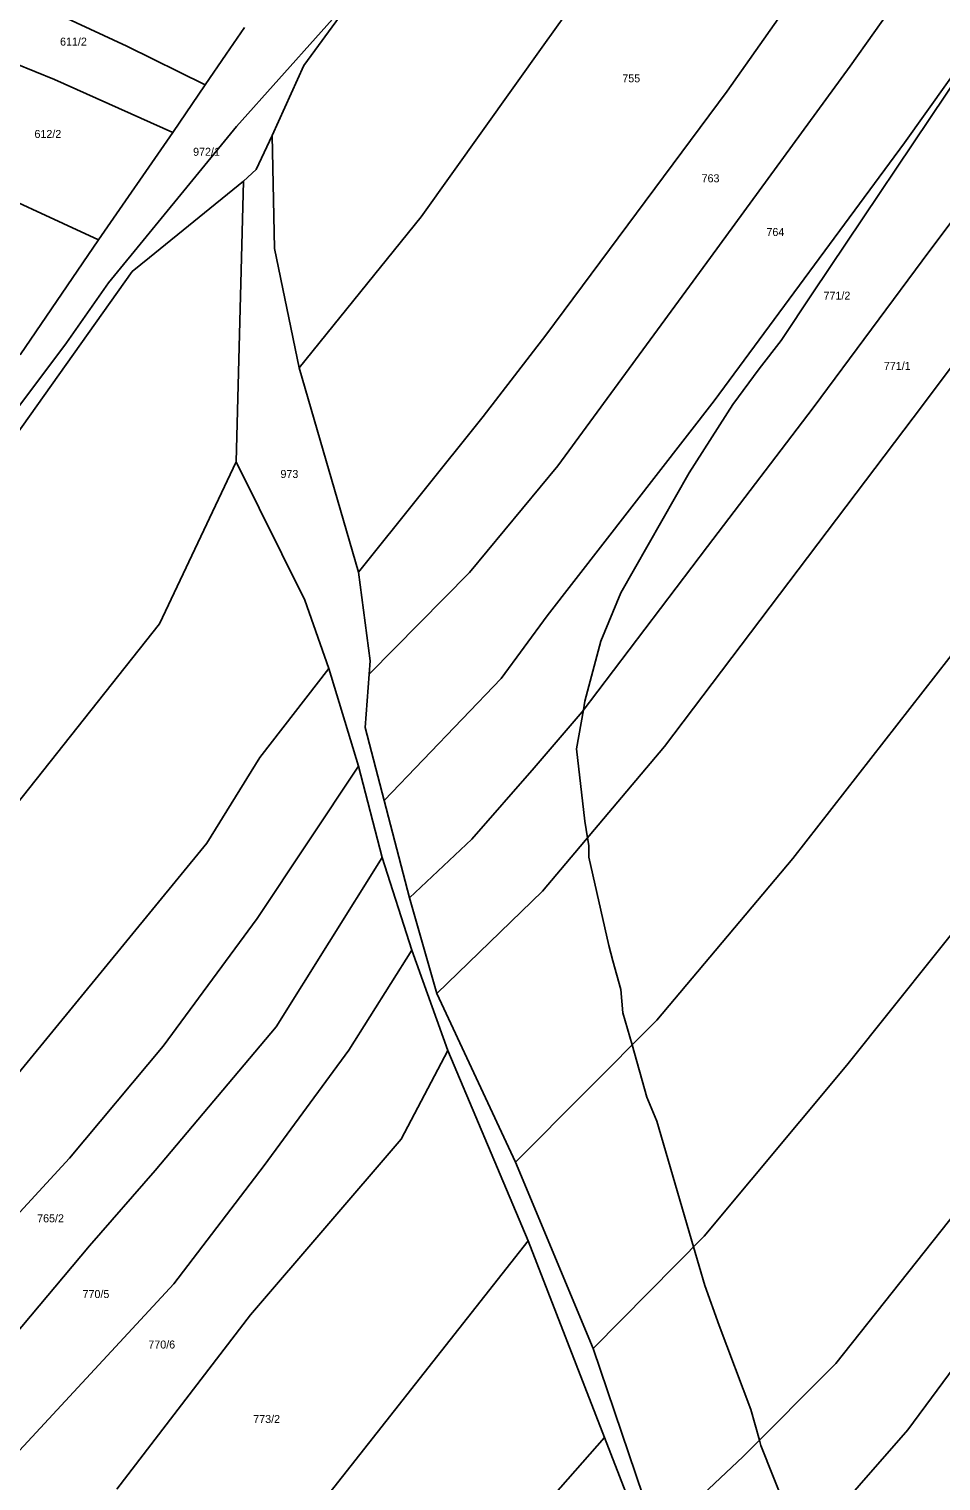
# Model space of a CAD drawing. Extents: x -749173 to -746119, y -1132678 to -1130338.
# Drawn here: x -748172.9 to -747979.1, y -1131515.5 to -1131207.1 of the extents above; entities that cross this region are included whole.
import ezdxf

# ---------------------------------------------------------------- set-up
doc = ezdxf.new("R2010")
doc.units = 0
for name, color, linetype in [('Vrstva 1', 7, 'Continuous'), ('Vrstva 18', 7, 'Continuous'), ('Vrstva 52', 7, 'Continuous'), ('Vrstva 6', 7, 'Continuous')]:
    doc.layers.add(name, color=color, linetype=linetype)

msp = doc.modelspace()

# ---------------------------------------------------------------- linework, layer by layer
at = {"layer": 'Vrstva 1'}
for points in [[(-748089.38, -1131180.54), (-748114.45, -1131214.85)], [(-748130.99, -1131212.41), (-748127.06, -1131206.76)], [(-748135.43, -1131218.94), (-748130.99, -1131212.41)], [(-748114.45, -1131214.85), (-748121.21, -1131229.7)], [(-748142.32, -1131229.06), (-748135.43, -1131218.94)], [(-748158.14, -1131251.87), (-748142.32, -1131229.06)], [(-748124.63, -1131236.91), (-748121.21, -1131229.7)], [(-748121.21, -1131229.7), (-748120.74, -1131253.68)], [(-748147.3, -1131255.64), (-748127.32, -1131239.4)], [(-748128.85, -1131299.01), (-748127.32, -1131239.4)], [(-748127.32, -1131239.4), (-748124.63, -1131236.91)], [(-748174.73, -1131276.29), (-748158.14, -1131251.87)], [(-748120.74, -1131253.68), (-748115.5, -1131279.07)], [(-748150.94, -1131258.6), (-748147.3, -1131255.64)], [(-748186.88, -1131309.09), (-748150.94, -1131258.6)], [(-748115.5, -1131279.07), (-748102.85, -1131322.48)], [(-748114.24, -1131328.44), (-748128.85, -1131299.01)], [(-748102.85, -1131322.48), (-748100.38, -1131341.3)], [(-748109.16, -1131342.95), (-748114.24, -1131328.44)], [(-748100.38, -1131341.3), (-748100.59, -1131344.15)], [(-748102.88, -1131363.67), (-748109.16, -1131342.95)], [(-748100.59, -1131344.15), (-748101.42, -1131355.5)], [(-748101.42, -1131355.5), (-748097.41, -1131370.99)], [(-748097.84, -1131383.08), (-748102.88, -1131363.67)], [(-748097.41, -1131370.99), (-748092.04, -1131391.66)], [(-748091.49, -1131402.75), (-748097.84, -1131383.08)], [(-748092.04, -1131391.66), (-748086.2, -1131411.99)], [(-748083.86, -1131424.07), (-748091.49, -1131402.75)], [(-748086.2, -1131411.99), (-748069.53, -1131447.82)], [(-748066.79, -1131464.53), (-748083.86, -1131424.07)], [(-748069.53, -1131447.82), (-748052.97, -1131487.38)], [(-748050.59, -1131506.3), (-748066.79, -1131464.53)], [(-748052.97, -1131487.38), (-748039.41, -1131527.57)], [(-748035.65, -1131544.85), (-748050.59, -1131506.3)]]:
    msp.add_lwpolyline(points, dxfattribs=at)
at = {"layer": 'Vrstva 52'}
for points in [[(-748101.82, -1131197.57), (-748128.75, -1131227.75), (-748156, -1131261), (-748164.94, -1131273.75), (-748191.69, -1131309.37), (-748224, -1131352.75), (-748231.25, -1131363), (-748232.94, -1131366.37), (-748237.19, -1131373.25), (-748246.12, -1131391.12), (-748246.24, -1131391.44), (-748246.42, -1131391.89), (-748259.31, -1131426.75), (-748266.56, -1131460), (-748269.56, -1131480), (-748271.25, -1131493.12), (-748271.53, -1131496.77), (-748272.98, -1131515.29), (-748274.31, -1131532.4)], [(-748009.25, -1131528.5), (-748017.37, -1131508), (-748017.68, -1131506.9), (-748019.5, -1131500.37), (-748026.25, -1131482.5), (-748029.25, -1131474), (-748031.65, -1131465.79), (-748039.44, -1131439.12), (-748041.56, -1131434), (-748044.74, -1131422.91), (-748046.69, -1131416.12), (-748047.12, -1131411.12), (-748048.79, -1131405.02), (-748049.69, -1131401.75), (-748053.94, -1131383), (-748053.94, -1131380.5), (-748054.19, -1131378.9), (-748054.75, -1131375.37), (-748056.5, -1131360), (-748055.07, -1131351.74), (-748054.75, -1131349.87), (-748051.37, -1131337.12), (-748047.12, -1131326.87), (-748032.62, -1131301.37), (-748023.31, -1131286.87), (-748017.75, -1131279.25), (-748013.06, -1131273.25), (-748006.31, -1131263.12), (-747974.37, -1131215.5)]]:
    msp.add_lwpolyline(points, dxfattribs=at)
at = {"layer": 'Vrstva 6'}
for points in [[(-748037.76, -1131174.55), (-748063.48, -1131210.43)], [(-748024.52, -1131220.29), (-747997.58, -1131182.04)], [(-747978.25, -1131186.55), (-747998.39, -1131214.99)], [(-747986.85, -1131231.25), (-747954.3, -1131185.56)], [(-748170.55, -1131202.15), (-748152.1, -1131210.73)], [(-748184.22, -1131210.98), (-748167.42, -1131217.79)], [(-748152.1, -1131210.73), (-748135.43, -1131218.94)], [(-748063.48, -1131210.43), (-748089.53, -1131247)], [(-748167.42, -1131217.79), (-748142.32, -1131229.06)], [(-747998.39, -1131214.99), (-748028.05, -1131255.6)], [(-748063.02, -1131272.11), (-748024.52, -1131220.29)], [(-747984.99, -1131289.67), (-747934.84, -1131222.88)], [(-747963.16, -1131229.8), (-747981.45, -1131254.14)], [(-748027.31, -1131286.05), (-747986.85, -1131231.25)], [(-748187.31, -1131238.43), (-748158.14, -1131251.87)], [(-748089.53, -1131247), (-748115.5, -1131279.07)], [(-747981.45, -1131254.14), (-748006.25, -1131287.53)], [(-748028.05, -1131255.6), (-748060.51, -1131299.88)], [(-748076.38, -1131289.39), (-748063.02, -1131272.11)], [(-748062.77, -1131331.73), (-748027.31, -1131286.05)], [(-748006.25, -1131287.53), (-748028.67, -1131317.02)], [(-748102.85, -1131322.48), (-748076.38, -1131289.39)], [(-748037.84, -1131359.52), (-747984.99, -1131289.67)], [(-748128.85, -1131299.01), (-748145.12, -1131333.41)], [(-748060.51, -1131299.88), (-748079.24, -1131322.55)], [(-748028.67, -1131317.02), (-748055.36, -1131352.12)], [(-748079.24, -1131322.55), (-748100.59, -1131344.15)], [(-748072.55, -1131345.05), (-748062.77, -1131331.73)], [(-747969.15, -1131330.2), (-748010.54, -1131383.33)], [(-748145.12, -1131333.41), (-748232.47, -1131443.55)], [(-748123.81, -1131361.87), (-748109.16, -1131342.95)], [(-748097.41, -1131370.99), (-748072.55, -1131345.05)], [(-748055.36, -1131352.12), (-748065.51, -1131364.02)], [(-748063.76, -1131390.25), (-748037.84, -1131359.52)], [(-748135.1, -1131380.02), (-748123.81, -1131361.87)], [(-748102.88, -1131363.67), (-748124.36, -1131396.05)], [(-748065.51, -1131364.02), (-748078.75, -1131379.21)], [(-748179.46, -1131434.11), (-748135.1, -1131380.02)], [(-748078.75, -1131379.21), (-748092.04, -1131391.66)], [(-748097.84, -1131383.08), (-748120.34, -1131419.08)], [(-748010.54, -1131383.33), (-748039.5, -1131417.64)], [(-748086.2, -1131411.99), (-748063.76, -1131390.25)], [(-747999.11, -1131427.19), (-747970.67, -1131391.64)], [(-748124.36, -1131396.05), (-748144.37, -1131423.16)], [(-748091.49, -1131402.75), (-748104.89, -1131424.02)], [(-748039.5, -1131417.64), (-748069.53, -1131447.82)], [(-748120.34, -1131419.08), (-748146.07, -1131449.57)], [(-748144.37, -1131423.16), (-748164.25, -1131446.94)], [(-748104.89, -1131424.02), (-748122.88, -1131448.54)], [(-748093.8, -1131442.91), (-748083.86, -1131424.07)], [(-748029.39, -1131463.51), (-747999.11, -1131427.19)], [(-747960.37, -1131438.84), (-748001.42, -1131490.57)], [(-748125.78, -1131480.26), (-748093.8, -1131442.91)], [(-748164.25, -1131446.94), (-748179.78, -1131463.77)], [(-748122.88, -1131448.54), (-748142.13, -1131473.68)], [(-748146.07, -1131449.57), (-748160.01, -1131465.57)], [(-748066.79, -1131464.53), (-748119.12, -1131530.98)], [(-748052.97, -1131487.38), (-748029.39, -1131463.51)], [(-747986.12, -1131504.66), (-747956.18, -1131464.19)], [(-748190.71, -1131502.08), (-748160.01, -1131465.57)], [(-748142.13, -1131473.68), (-748180.26, -1131514.82)], [(-748154.21, -1131517.27), (-748125.78, -1131480.26)], [(-748001.42, -1131490.57), (-748021.11, -1131510.35)], [(-748006.8, -1131528.34), (-747986.12, -1131504.66)], [(-748088.51, -1131549.4), (-748050.59, -1131506.3)], [(-748021.11, -1131510.35), (-748039.41, -1131527.57)]]:
    msp.add_lwpolyline(points, dxfattribs=at)

# ---------------------------------------------------------------- texts
at = {"layer": 'Vrstva 18'}
for s, p in [('611/2', (-748166.27, -1131210.59)), ('755', (-748046.8, -1131218.39)), ('612/2', (-748171.71, -1131230.21)), ('972/1', (-748138, -1131234)), ('763', (-748029.95, -1131239.63)), ('764', (-748016.17, -1131251.04)), ('771/2', (-748004.04, -1131264.57)), ('771/1', (-747991.22, -1131279.48)), ('973', (-748119.44, -1131302.45)), ('765/2', (-748171.14, -1131460.59)), ('770/5', (-748161.49, -1131476.68)), ('770/6', (-748147.51, -1131487.41)), ('773/2', (-748125.22, -1131503.23))]:
    msp.add_text(s, height=1.7, dxfattribs=at).set_placement(p)

doc.saveas('drawing.dxf')
